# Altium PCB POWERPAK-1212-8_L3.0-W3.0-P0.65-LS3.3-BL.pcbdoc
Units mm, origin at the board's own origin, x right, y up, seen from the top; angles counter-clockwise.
Board outline 16.04 x 16.74 mm, 2 copper layers (Top Layer, Bottom Layer), stack 0 mm thick; 1 components, 0 nets, 9 pads, 0 vias.
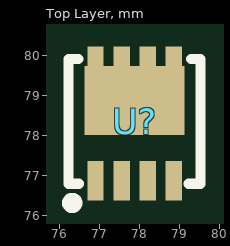
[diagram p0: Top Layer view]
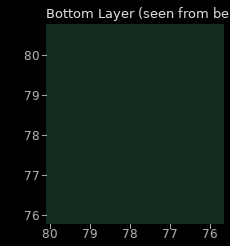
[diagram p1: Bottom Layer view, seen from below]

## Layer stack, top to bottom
Top Layer: signal copper (thickness not stored)
Bottom Layer: signal copper (thickness not stored)

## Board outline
85.887,69.85 69.85,69.85 69.85,86.587 85.887,86.587

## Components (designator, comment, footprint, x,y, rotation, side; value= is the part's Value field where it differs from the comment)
U? "" POWERPAK-1212-8_L3.0-W3.0-P0.65-LS3.3-BL 77.887,78.367 r0 top

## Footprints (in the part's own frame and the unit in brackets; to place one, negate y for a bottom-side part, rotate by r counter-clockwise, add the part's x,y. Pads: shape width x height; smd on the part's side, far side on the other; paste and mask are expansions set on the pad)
POWERPAK-1212-8_L3.0-W3.0-P0.65-LS3.3-BL [mil]
  rect 15.98x39.02 smd paste-3937.01 mask+1.97: 1(-38.39,-58.5) 2(-12.79,-58.5) 3(12.8,-58.5) 4(38.39,-58.5)
  rect 15.98x30 smd paste-3937.01 mask+1.97: 5(38.39,58.5) 6(12.8,58.5) 7(-12.79,58.5) 8(-38.39,58.5)
  rect 98.42x67.99 smd paste-3937.01 mask+1.97: 8(0,20.5)
  silkscreen extent -66,-85 65,61

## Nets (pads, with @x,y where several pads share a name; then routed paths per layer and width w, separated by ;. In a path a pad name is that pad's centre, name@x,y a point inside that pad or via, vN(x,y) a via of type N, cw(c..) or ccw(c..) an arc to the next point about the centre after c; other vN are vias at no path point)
pads on no net: U?.1 U?.2 U?.3 U?.4 U?.5 U?.6 U?.7 U?.8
